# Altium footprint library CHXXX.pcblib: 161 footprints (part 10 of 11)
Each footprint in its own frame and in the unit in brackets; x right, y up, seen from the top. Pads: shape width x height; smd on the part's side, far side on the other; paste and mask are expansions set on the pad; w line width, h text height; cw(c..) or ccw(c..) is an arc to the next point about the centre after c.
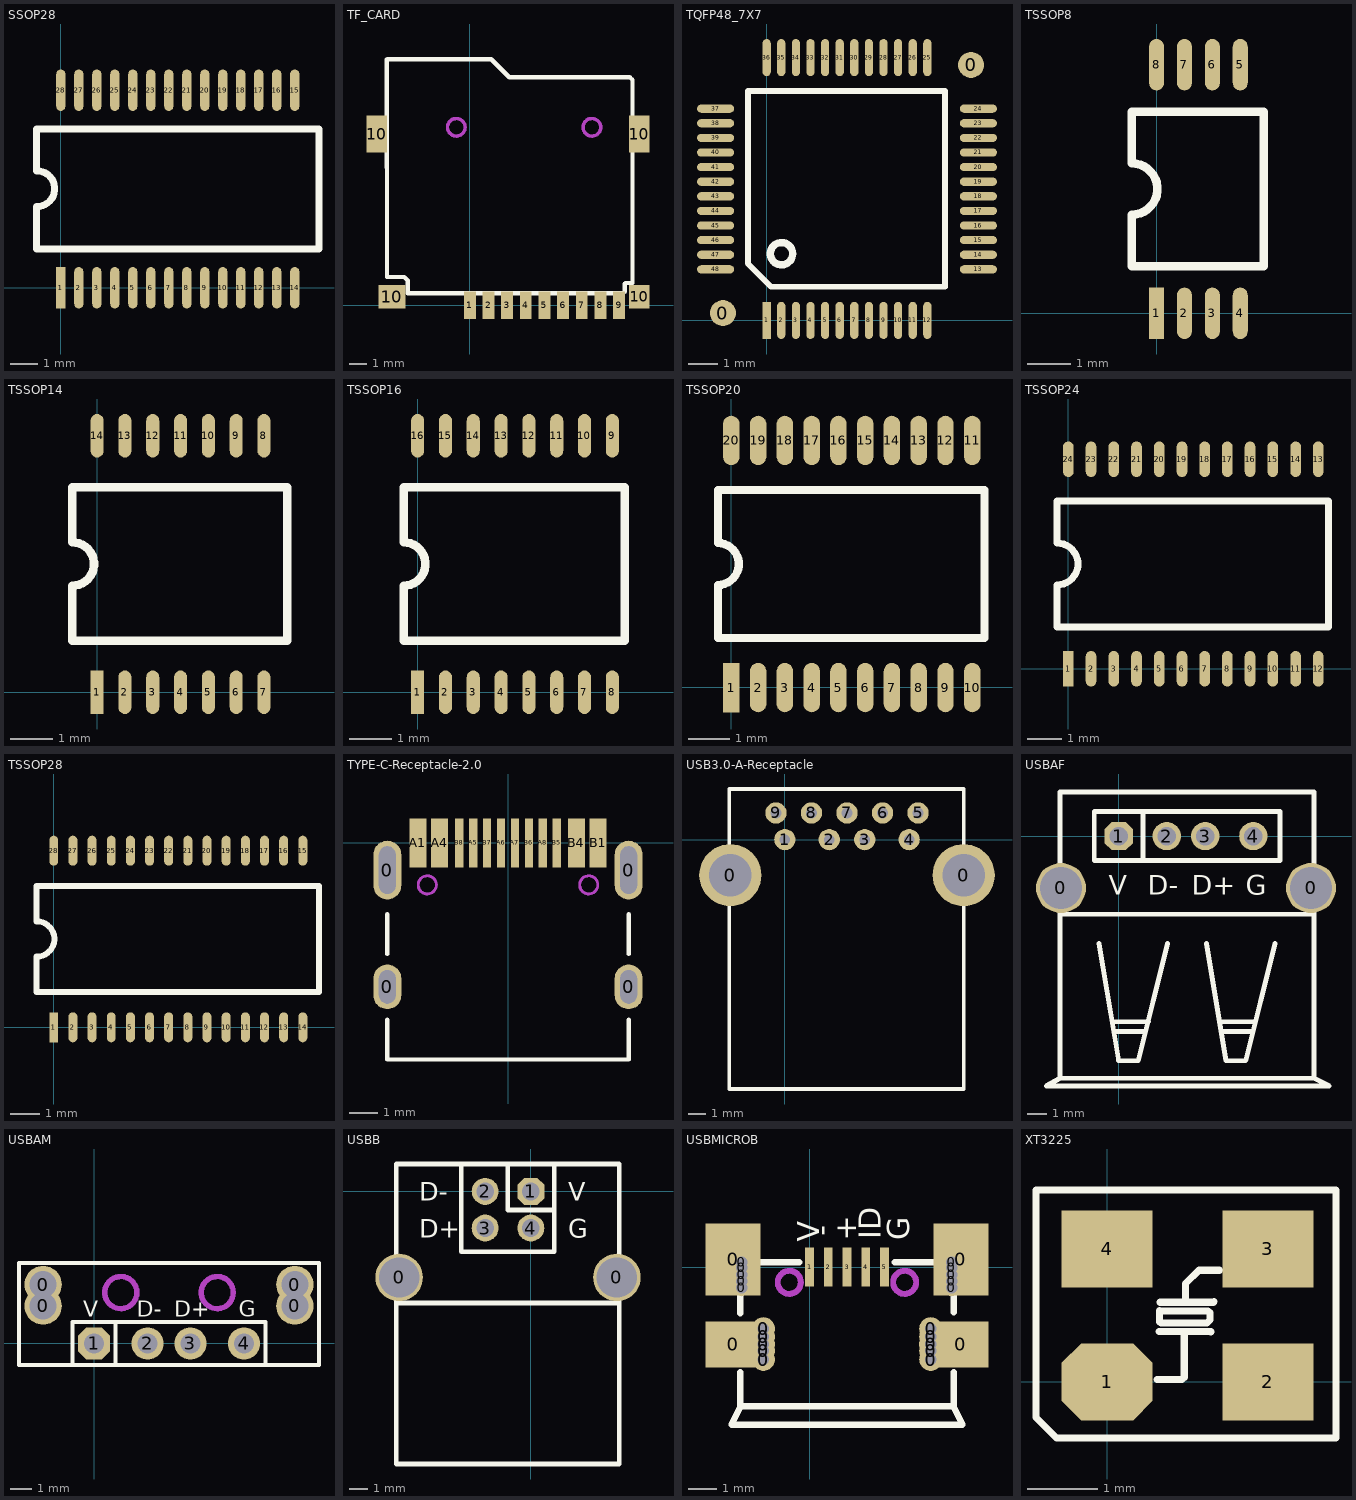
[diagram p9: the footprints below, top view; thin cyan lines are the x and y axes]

## SSOP28 [mm]
pads (28):
  rect 0.33x1.5 smd: 1(0,0)
  oval 0.33x1.5 smd: 2(0.65,0) 3(1.3,0) 4(1.95,0) 5(2.6,0) 6(3.25,0) 7(3.9,0) 8(4.55,0) 9(5.2,0) 10(5.85,0) 11(6.5,0) 12(7.15,0) 13(7.8,0) 14(8.45,0) 15(8.45,7.136) 16(7.8,7.136) 17(7.15,7.136) 18(6.5,7.136) 19(5.85,7.136) 20(5.2,7.136) 21(4.55,7.136) 22(3.9,7.136) 23(3.25,7.136) 24(2.6,7.136) 25(1.95,7.136) 26(1.3,7.136) 27(0.65,7.136) 28(0,7.136)
TopOverlay:
  lines w0.254: -0.875,4.223 -0.875,5.727 9.325,5.727 9.325,1.409 -0.875,1.409 -0.875,2.933 ccw(c-0.865,3.578) -0.872,4.223

## TF_CARD [mm]
pads (13):
  rect 0.7x1.6 smd: 1(0,0) 2(1.1,0) 3(2.2,0) 4(3.3,0) 5(4.4,0) 6(5.5,0) 7(6.6,0) 8(7.7,0) 9(8.8,0)
  rect 1.2x2.2 smd: 10(-5.5,10.1) 10(10,10.1)
  rect 1.6x1.4 smd: 10(-4.6,0.5)
  rect 1.2x1.4 smd: 10(10,0.5)
TopOverlay:
  lines w0.254: -4.9,14.5 -4.884,1.667 -3.868,1.667 -3.665,1.464 -3.665,0.702 9.035,0.702 9.136,0.804 9.136,1.261 9.187,1.312 9.594,1.312 ; -4.88,14.52 1.262,14.52 2.329,13.453 9.441,13.453 9.543,13.351 ; 9.594,1.313 9.594,13.302
KeepOutLayer:
  circle w0.2: c7.2,10.5 r0.52
  circle w0.2: c-0.8,10.5 r0.52
Mechanical1:
  circle w0.2: c7.2,10.5 r0.52
  circle w0.2: c-0.8,10.5 r0.52

## TQFP48_7X7 [mm]
pads (50):
  round 0.889 smd: 0(-1.496,0.254) 0(6.996,8.746)
  rect 0.28x1.27 smd mask+0.051: 1(0,0)
  oval 0.28x1.27 smd mask+0.051: 2(0.5,0) 3(1,0) 4(1.5,0) 5(2,0) 6(2.5,0) 7(3,0) 8(3.5,0) 9(4,0) 10(4.5,0) 11(5,0) 12(5.5,0) 25(5.5,9) 26(5,9) 27(4.5,9) 28(4,9) 29(3.5,9) 30(3,9) 31(2.5,9) 32(2,9) 33(1.5,9) 34(1,9) 35(0.5,9) 36(0,9)
  oval 1.27x0.28 smd mask+0.051: 13(7.25,1.75) 14(7.25,2.25) 15(7.25,2.75) 16(7.25,3.25) 17(7.25,3.75) 18(7.25,4.25) 19(7.25,4.75) 20(7.25,5.25) 21(7.25,5.75) 22(7.25,6.25) 23(7.25,6.75) 24(7.25,7.25) 37(-1.75,7.25) 38(-1.75,6.75) 39(-1.75,6.25) 40(-1.75,5.75) 41(-1.75,5.25) 42(-1.75,4.75) 43(-1.75,4.25) 44(-1.75,3.75) 45(-1.75,3.25) 46(-1.75,2.75) 47(-1.75,2.25) 48(-1.75,1.75)
TopOverlay:
  circle w0.254: c0.508,2.286 r0.381
  lines w0.2: -0.646,1.947 0.148,1.154
  lines w0.203: -0.646,1.947 -0.646,7.859 6.111,7.859 6.111,1.154 0.148,1.154

## TSSOP8 [mm]
pads (8):
  rect 0.35x1.2 smd mask+0.051: 1(0,0)
  oval 0.35x1.2 smd mask+0.051: 2(0.65,0) 3(1.3,0) 4(1.951,0) 5(1.951,5.794) 6(1.3,5.794) 7(0.65,5.794) 8(0,5.794)
TopOverlay:
  lines w0.2: -0.579,1.1 -0.579,2.297 ccw(c-0.579,2.897) -0.579,3.497 -0.579,4.694 2.497,4.694 2.497,1.1 -0.579,1.1

## TSSOP14 [mil]
pads (14):
  rect 12x40 smd: 1(0,0)
  oval 12x40 smd: 2(25.6,0) 3(51.2,0) 4(76.8,0) 5(102.4,0) 6(128,0) 7(153.5,0) 8(153.5,236) 9(128,236) 10(102.4,236) 11(76.8,236) 12(51.2,236) 13(25.6,236) 14(0,236)
TopOverlay:
  lines w7.87: -22.8,47.24 175.11,47.24 175.11,188.76 -22.8,188.76 -22.8,138 cw(c-22.8,118) -22.8,98 -22.8,47.24

## TSSOP16 [mil]
pads (16):
  rect 12x40 smd: 1(0,0)
  oval 12x40 smd: 2(25.6,0) 3(51.2,0) 4(76.8,0) 5(102.4,0) 6(128,0) 7(153.5,0) 8(179.1,0) 9(179.1,236) 10(153.5,236) 11(128,236) 12(102.4,236) 13(76.8,236) 14(51.2,236) 15(25.6,236) 16(0,236)
TopOverlay:
  lines w7.87: -12.79,47.24 -12.79,98 ccw(c-12.79,118) -12.79,138 -12.79,188.76 190.71,188.76 190.71,47.24 -12.79,47.24

## TSSOP20 [mm]
height 1.3
pads (20):
  rect 0.4x1.2 smd mask+0.05: 1(0,-0.003)
  oval 0.4x1.2 smd mask+0.05: 2(0.65,-0.003) 3(1.3,-0.003) 4(1.951,-0.003) 5(2.601,-0.003) 6(3.251,-0.003) 7(3.899,-0.003) 8(4.549,-0.003) 9(5.199,-0.003) 10(5.85,-0.003) 11(5.85,5.997) 12(5.199,5.997) 13(4.549,5.997) 14(3.899,5.997) 15(3.251,5.997) 16(2.601,5.997) 17(1.951,5.997) 18(1.3,5.997) 19(0.65,5.997) 20(0,5.997)
TopOverlay:
  lines w0.2: -0.325,1.2 -0.325,2.489 ccw(c-0.325,2.997) -0.325,3.505 -0.325,4.794 6.145,4.794 6.145,1.2 -0.325,1.2

## TSSOP24 [mil]
pads (24):
  rect 12x40 smd: 1(0,0)
  oval 12x40 smd: 2(25.6,0) 3(51.2,0) 4(76.8,0) 5(102.4,0) 6(128,0) 7(153.5,0) 8(179.1,0) 9(204.7,0) 10(230.3,0) 11(256,0) 12(281.5,0) 13(281.5,236) 14(256,236) 15(230.3,236) 16(204.7,236) 17(179.1,236) 18(153.5,236) 19(128,236) 20(102.4,236) 21(76.8,236) 22(51.2,236) 23(25.6,236) 24(0,236)
TopOverlay:
  lines w7.87: -12.79,47.24 293.11,47.24 293.11,188.76 -12.79,188.76 -12.79,141.62 cw(c-12.79,118) -12.8,94.38 -12.79,47.24

## TSSOP28 [mil]
pads (28):
  rect 12x40 smd: 1(0,0)
  oval 12x40 smd: 2(25.6,0) 3(51.2,0) 4(76.8,0) 5(102.4,0) 6(128,0) 7(153.5,0) 8(179.1,0) 9(204.7,0) 10(230.3,0) 11(256,0) 12(281.5,0) 13(307.2,0) 14(332.7,0) 15(332.7,236) 16(307.2,236) 17(281.5,236) 18(256,236) 19(230.3,236) 20(204.7,236) 21(179.1,236) 22(153.5,236) 23(128,236) 24(102.4,236) 25(76.8,236) 26(51.2,236) 27(25.6,236) 28(0,236)
TopOverlay:
  lines w7.87: -22.8,47.24 -22.8,94.38 ccw(c-22.8,118) -22.8,141.62 -22.8,188.76 354.31,188.76 354.31,47.24 -22.8,47.24

## TYPE-C-Receptacle-2.0 [mm]
pads (16):
  oval 1x1.6 hole 0.6 slot 1.2 at 90 deg: 0(-4.32,-5.15) 0(4.32,-5.15)
  oval 1x2.1 hole 0.6 slot 1.7 at 90 deg: 0(-4.32,-0.97) 0(4.32,-0.97)
  rect 0.6x1.75 smd mask+0.051: A1(-3.225,0) A4(-2.45,0) B1(3.225,0) B4(2.45,0)
  rect 0.3x1.75 smd mask+0.051: A5(-1.25,0) A6(-0.25,0) A7(0.25,0) A8(1.25,0) B5(1.75,0) B6(0.75,0) B7(-0.75,0) B8(-1.75,0)
TopOverlay:
  lines w0.152: -4.32,-6.325 -4.32,-7.75 4.32,-7.75 4.32,-6.325 ; -4.32,-3.975 -4.32,-2.55 ; 4.32,-3.975 4.32,-2.55
KeepOutLayer:
  circle w0.1: c-2.89,-1.5 r0.325
  circle w0.1: c2.89,-1.5 r0.325
Mechanical1:
  circle w0.102: c-2.89,-1.5 r0.325
  circle w0.102: c2.89,-1.5 r0.325

## USB3.0-A-Receptacle [mm]
pads (11):
  round 3.5 hole 2.4: 0(-3.07,-2) 0(10.07,-2)
  round 1.2 hole 0.6: 1(0,0) 2(2.5,0) 3(4.5,0) 4(7,0) 5(7.5,1.5) 6(5.5,1.5) 7(3.5,1.5) 8(1.5,1.5) 9(-0.5,1.5)
TopOverlay:
  lines w0.2: -3.138,2.85 -3.138,-14.041 10.07,-14.041 10.07,2.85 -3.13,2.85 ; -1.33,2.85 1.245,2.85
BottomOverlay:
  text "T+" at -0.127,-1.041 h0.8
  text "T-" at 1.803,-1.041 h0.8
  text "G" at 3.886,-1.041 h0.8
  text "R+" at 5.969,-1.041 h0.8
  text "R-" at 7.772,-1.041 h0.8
  text "G" at 7.315,-3.302 h0.8
  text "D+" at 4.775,-3.302 h0.8
  text "D-" at 2.743,-3.302 h0.8
  text "V" at 0.406,-3.302 h0.8

## USBAF [mm]
pads (6):
  round 2.6 hole 2.2: 0(-3,-2.7) 0(10,-2.7)
  oct 1.473x1.473 hole 0.965: 1(0,0)
  round 1.473 hole 0.965: 2(2.5,0) 3(4.5,0) 4(7,0)
TopOverlay:
  lines w0.254: -3.048,-4.064 10.16,-4.064 ; -1.016,-5.588 0,-11.684 1.016,-11.684 2.54,-5.588 ; -0.33,-9.652 1.549,-9.652 ; -0.203,-10.16 1.321,-10.16 ; 1.27,-1.27 1.27,1.27 ; 4.572,-5.588 5.588,-11.684 6.604,-11.684 8.128,-5.588 ; 5.232,-9.652 7.112,-9.652 ; 5.359,-10.16 6.883,-10.16 ; -3.048,-12.59 -3.752,-12.99 10.948,-12.99 10.16,-12.59 ; -3.048,-12.59 10.16,-12.59 ; -3.048,-12.59 -3.048,2.286 10.16,2.286 10.16,-12.59 ; -1.27,-1.27 -1.27,1.27 8.382,1.27 8.382,-1.27 -1.27,-1.27
  text "G" at 6.604,-3.048 h1.02
  text "V" at -0.508,-3.048 h1.02
  text "D+" at 3.81,-3.048 h1.02
  text "D-" at 1.524,-3.048 h1.02

## USBAM [mil]
pads (8):
  round 70 hole 50: 0(-95,70) 0(-95,110) 0(375,70) 0(375,110)
  oct 60x60 hole 38: 1(0,0)
  round 60 hole 38: 2(100,0) 3(180,0) 4(280,0)
TopOverlay:
  lines w8: -40,-40 -40,40 320,40 320,-40 ; 40,-40 40,40 ; -140,-40 -140,150 420,150 420,-40 -140,-40
  text "D-" at 80,50 h30
  text "D+" at 150,50 h30
  text "V" at -20,50 h30
  text "G" at 270,50 h30
KeepOutLayer:
  circle w10: c50,95 r30
  circle w10: c230,95 r30
Mechanical1:
  circle w10: c230,95 r30
  circle w10: c50,95 r30

## USBB [mm]
pads (6):
  round 2.6 hole 2.2: 0(-7.2,-4.7) 0(4.7,-4.7)
  oct 1.473x1.473 hole 0.965: 1(0,0)
  round 1.473 hole 0.965: 2(-2.5,0) 3(-2.5,-2) 4(0,-2)
TopOverlay:
  lines w0.254: -7.366,-6.096 4.826,-6.096 ; -7.366,-3.302 -7.366,1.5 4.826,1.5 4.826,-3.58 ; -7.366,-3.048 -7.366,-14.9 4.826,-14.9 4.826,-1.016 ; -3.81,1.5 -3.81,-3.302 1.27,-3.302 1.27,1.5 ; -1.27,1.5 -1.27,-1.016 1.27,-1.016
  text "G" at 2.032,-2.54 h1.02
  text "V" at 2.032,-0.508 h1.02
  text "D+" at -6.096,-2.54 h1.02
  text "D-" at -6.096,-0.508 h1.02

## USBMICROB [mm]
pads (29):
  rect 1.9x1.6 smd: 0(-2.65,-2.675) 0(5.25,-2.675)
  rect 1.9x2.5 smd: 0(-2.65,0.271) 0(5.25,0.271)
  round 0.6 hole 0.4: 0(-2.349,-0.708) 0(-2.349,-0.483) 0(-2.349,-0.254) 0(-2.349,-0.025) 0(-2.349,0.178) 0(4.927,-0.708) 0(4.928,-0.483) 0(4.928,-0.254) 0(4.928,-0.025) 0(4.928,0.178)
  round 0.8 hole 0.4: 0(-1.6,-2.675) 0(-1.596,-3.2) 0(-1.596,-2.896) 0(-1.596,-2.413) 0(-1.596,-2.134) 0(4.2,-2.675) 0(4.204,-3.2) 0(4.204,-2.896) 0(4.204,-2.413) 0(4.204,-2.134)
  rect 0.3x1.35 smd: 1(0,0) 2(0.65,0) 3(1.3,0) 4(1.95,0) 5(2.6,0)
TopOverlay:
  lines w0.229: -2.4,-3.65 -2.4,-4.825 ; -2.4,-1.592 -2.4,0.175 -0.351,0.175 ; 2.951,0.175 5,0.175 5,-1.558 ; 5,-3.65 5,-4.825 ; -2.4,-4.825 -2.7,-5.455 5.3,-5.455 5,-4.825 ; -2.4,-4.825 5,-4.825
  text "+" at 1.626,0.914 h0.76
  text "-" at 0.203,1.448 h0.76
  text "V" at 0.33,0.889 h0.76
  text "G" at 3.454,0.94 h0.76
  text "ID" at 2.464,0.965 h0.76
KeepOutLayer:
  circle w0.203: c-0.7,-0.525 r0.4
  circle w0.203: c3.3,-0.525 r0.4
Mechanical1:
  circle w0.203: c3.3,-0.525 r0.4
  circle w0.203: c-0.7,-0.525 r0.4

## XT3225 [mm]
pads (4):
  oct 1.3x1.1 smd: 1(0,0)
  rect 1.3x1.1 smd: 2(2.3,0) 3(2.3,1.9) 4(0,1.9)
TopOverlay:
  lines w0.102: 0.713,0.033 1.073,0.033 1.104,0.064 1.104,0.66 ; 0.744,0.722 1.476,0.722 1.482,0.716 ; 0.75,1.013 1.445,1.013 1.47,0.988 1.47,0.883 1.426,0.84 0.769,0.84 0.75,0.858 0.75,1.019 ; 0.757,1.137 1.519,1.137 1.532,1.15 ; 1.122,1.205 1.122,1.404 1.315,1.596 1.606,1.596 ; -1.017,-0.512 -0.725,-0.804 3.274,-0.804 3.274,2.743 -1.017,2.743 -1.017,-0.512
